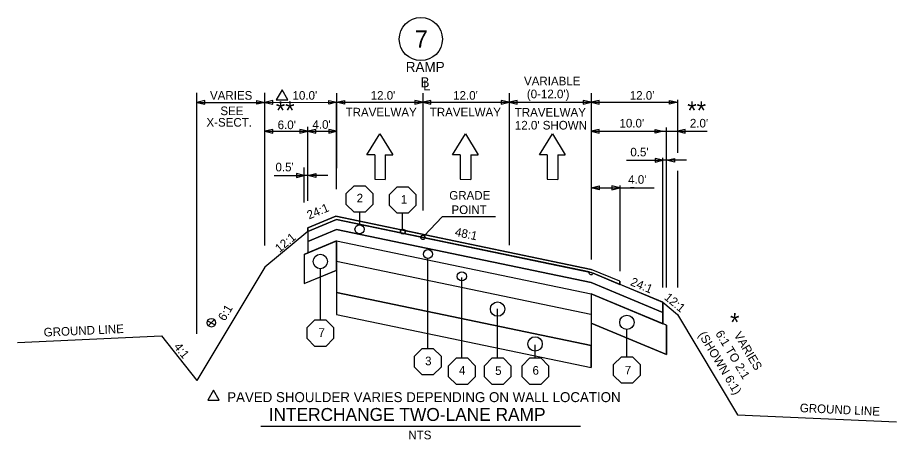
# Model space of a CAD drawing. Extents: x 4932 to 5887, y 4809 to 5473.
# Drawn here: x 5068.2 to 5190.4, y 5247.4 to 5306.2 of the extents above; entities that cross this region are included whole.
import ezdxf

# ---------------------------------------------------------------- set-up
doc = ezdxf.new("R2010")
doc.units = 0
for name, color, linetype in [('Level 20', 7, 'Continuous'), ('Level 25', 7, 'Continuous'), ('RD_QTY_Intermediate', 7, 'Continuous'), ('RD_QTY_OGFC', 7, 'Continuous'), ('RD_QTY_Stab_Agg_2', 7, 'Continuous'), ('RD_QTY_Sub_Base', 7, 'Continuous'), ('RD_QTY_Surf_Course', 7, 'Continuous'), ('RD_SHT_Typical', 7, 'Continuous'), ('RD_TX_TypSect', 7, 'Continuous'), ('RD_XS_ExGround', 7, 'Continuous'), ('typical_on', 7, 'Continuous')]:
    doc.layers.add(name, color=color, linetype=linetype)

msp = doc.modelspace()

# ---------------------------------------------------------------- linework, layer by layer
at = {"layer": 'Level 20'}
for p, q in [((5116.76, 5287.06), (5118.58, 5289.98)), ((5118.58, 5289.98), (5120.36, 5287.05)), ((5128.65, 5287.06), (5130.47, 5289.98)), ((5130.47, 5289.98), (5132.26, 5287.05)), ((5140.75, 5287.06), (5142.57, 5289.98)), ((5142.57, 5289.98), (5144.35, 5287.05)), ((5117.85, 5287.06), (5116.76, 5287.06)), ((5117.85, 5287.06), (5117.85, 5283.66)), ((5119.31, 5287.05), (5120.36, 5287.05)), ((5119.31, 5287.05), (5119.31, 5283.65)), ((5129.74, 5287.06), (5128.65, 5287.06)), ((5129.74, 5287.06), (5129.74, 5283.66)), ((5131.2, 5287.05), (5132.26, 5287.05)), ((5131.2, 5287.05), (5131.2, 5283.65)), ((5141.84, 5287.06), (5140.75, 5287.06)), ((5141.84, 5287.06), (5141.84, 5283.66)), ((5143.3, 5287.05), (5144.35, 5287.05)), ((5143.3, 5287.05), (5143.3, 5283.65)), ((5117.85, 5283.66), (5119.31, 5283.65)), ((5129.74, 5283.66), (5131.2, 5283.65)), ((5141.84, 5283.66), (5143.3, 5283.65))]:
    msp.add_line(p, q, dxfattribs=at)
at = {"layer": 'Level 25'}
for p, q in [((5127.23, 5278.45), (5124.75, 5275.8)), ((5134.63, 5278.45), (5127.23, 5278.45))]:
    msp.add_line(p, q, dxfattribs=at)
msp.add_circle((5124.27, 5303.18), 3, dxfattribs=at)
at = {"layer": 'RD_QTY_Intermediate'}
for p, q in [((5112.56, 5276.67), (5108.56, 5275)), ((5147.95, 5269.3), (5112.56, 5276.67)), ((5108.56, 5273.41), (5112.56, 5275.07)), ((5108.56, 5275), (5108.56, 5273.41)), ((5112.56, 5275.07), (5147.95, 5267.7)), ((5157.95, 5265.13), (5147.95, 5269.3)), ((5147.95, 5267.7), (5157.95, 5263.53)), ((5157.95, 5263.53), (5157.95, 5265.13))]:
    msp.add_line(p, q, dxfattribs=at)
at = {"layer": 'RD_QTY_OGFC'}
for p, q in [((5112.45, 5278.52), (5108.56, 5276.9)), ((5121.55, 5276.62), (5112.45, 5278.52)), ((5108.56, 5276.4), (5112.56, 5278.07)), ((5112.56, 5278.07), (5121.46, 5276.21)), ((5108.56, 5276.9), (5108.56, 5276.4))]:
    msp.add_line(p, q, dxfattribs=at)
msp.add_arc((5121.76, 5276.37), 0.332, 129.2008, 207.76, dxfattribs=at)
at = {"layer": 'RD_QTY_Stab_Agg_2'}
for p, q in [((5112.56, 5275.07), (5108.56, 5273.41)), ((5112.55, 5272.24), (5112.56, 5275.07)), ((5108.56, 5273.41), (5108.06, 5273.2)), ((5108.06, 5273.2), (5108.06, 5269.14)), ((5112.55, 5272.23), (5112.53, 5272.24)), ((5112.55, 5271.02), (5112.55, 5272.23)), ((5108.06, 5269.14), (5112.55, 5271.01)), ((5112.55, 5271.01), (5112.55, 5271.02)), ((5147.95, 5263.64), (5158.45, 5259.27)), ((5158.45, 5259.27), (5158.45, 5263.33))]:
    msp.add_line(p, q, dxfattribs=at)
for points in [[(5112.53, 5272.24), (5112.55, 5272.24)], [(5147.95, 5267.7), (5147.95, 5264.86), (5147.95, 5263.64)], [(5158.45, 5263.33), (5157.95, 5263.53), (5147.95, 5267.7)]]:
    msp.add_lwpolyline(points, dxfattribs=at)
at = {"layer": 'RD_QTY_Sub_Base'}
for p, q in [((5112.54, 5267.91), (5112.53, 5264.81)), ((5147.95, 5260.53), (5112.54, 5267.91)), ((5112.53, 5264.81), (5147.95, 5257.43)), ((5147.95, 5257.43), (5147.95, 5260.53))]:
    msp.add_line(p, q, dxfattribs=at)
at = {"layer": 'RD_QTY_Surf_Course'}
for p, q in [((5112.56, 5278.07), (5108.56, 5276.4)), ((5147.66, 5270.75), (5112.56, 5278.07)), ((5108.56, 5275), (5112.56, 5276.67)), ((5108.56, 5276.4), (5108.56, 5275)), ((5112.56, 5276.67), (5147.95, 5269.3)), ((5157.95, 5266.51), (5148.23, 5270.58)), ((5147.95, 5269.3), (5157.95, 5265.13)), ((5157.95, 5265.13), (5157.95, 5266.51))]:
    msp.add_line(p, q, dxfattribs=at)
msp.add_circle((5115.74, 5276.7), 0.63, dxfattribs=at)
msp.add_arc((5147.95, 5270.69), 0.3, 168.2335, 337.3133, dxfattribs=at)
at = {"layer": 'RD_SHT_Typical'}
for p, q in [((5108.56, 5276.9), (5112.45, 5278.52)), ((5108.56, 5276.4), (5112.56, 5278.07)), ((5108.56, 5276.4), (5102.57, 5271.4)), ((5108.56, 5276.4), (5108.56, 5276.9)), ((5108.56, 5275), (5112.56, 5276.67)), ((5108.56, 5276.4), (5108.56, 5273.41)), ((5121.96, 5276.11), (5124.26, 5275.63)), ((5124.87, 5275.93), (5122.05, 5276.52)), ((5124.75, 5275.8), (5124.87, 5275.93)), ((5124.87, 5275.93), (5124.75, 5275.8)), ((5147.95, 5271.12), (5124.87, 5275.93)), ((5108.06, 5273.2), (5112.58, 5275.08)), ((5112.53, 5275.09), (5112.53, 5264.81)), ((5124.85, 5275.51), (5147.66, 5270.75)), ((5108.06, 5273.2), (5108.06, 5269.14)), ((5102.57, 5271.4), (5093.12, 5255.66)), ((5108.06, 5269.14), (5112.58, 5271.02)), ((5151.95, 5269.45), (5147.95, 5271.12)), ((5151.95, 5269.45), (5147.95, 5271.12)), ((5147.66, 5270.75), (5147.95, 5270.69)), ((5157.95, 5266.53), (5147.95, 5270.69)), ((5157.95, 5265.13), (5147.95, 5269.3)), ((5151.95, 5269.45), (5151.95, 5269.03)), ((5151.95, 5269.03), (5151.95, 5269.45)), ((5147.95, 5267.7), (5147.95, 5257.43)), ((5158.45, 5263.33), (5147.95, 5267.7)), ((5157.95, 5266.53), (5159.95, 5264.85)), ((5157.95, 5266.51), (5157.95, 5263.53)), ((5158.45, 5259.27), (5147.95, 5263.64)), ((5159.95, 5264.85), (5168.33, 5250.88)), ((5158.45, 5263.33), (5158.45, 5259.27)), ((5088.18, 5261.84), (5093.12, 5255.66))]:
    msp.add_line(p, q, dxfattribs=at)
for points in [[(5112.45, 5278.52), (5147.95, 5271.12)], [(5112.56, 5278.07), (5147.95, 5270.69)], [(5112.56, 5276.67), (5147.95, 5269.3)], [(5112.56, 5275.07), (5147.95, 5267.7)], [(5124.75, 5275.8), (5124.75, 5275.8)], [(5112.53, 5272.24), (5147.93, 5264.86)], [(5147.95, 5270.69), (5148.23, 5270.58), (5151.95, 5269.02)], [(5151.95, 5269.02), (5151.95, 5269.03)], [(5112.53, 5267.91), (5147.95, 5260.53)], [(5112.53, 5264.81), (5147.95, 5257.43)]]:
    msp.add_lwpolyline(points, dxfattribs=at)
for centre, radius, start, end in [((5121.76, 5276.37), 0.332, 308.7071, 27.2663), ((5124.56, 5275.57), 0.3, 50.3399, 168.2335), ((5124.56, 5275.57), 0.3, 348.2335, 50.3399)]:
    msp.add_arc(centre, radius, start, end, dxfattribs=at)
at = {"layer": 'RD_TX_TypSect'}
for p, q in [((5093.12, 5262.15), (5093.12, 5295.7)), ((5102.57, 5274.42), (5102.57, 5295.7)), ((5112.56, 5295.67), (5112.56, 5285.2)), ((5124.56, 5295.67), (5124.56, 5279.32)), ((5136.55, 5295.67), (5136.55, 5274.5)), ((5147.95, 5295.67), (5147.95, 5272.5)), ((5093.12, 5294.37), (5102.57, 5294.37)), ((5102.57, 5294.37), (5112.56, 5294.38)), ((5112.56, 5282.28), (5112.56, 5294.5)), ((5112.56, 5294.38), (5124.56, 5294.38)), ((5124.56, 5294.38), (5136.55, 5294.38)), ((5136.55, 5294.38), (5147.95, 5294.38)), ((5147.95, 5294.38), (5159.95, 5294.38)), ((5159.95, 5294.72), (5159.95, 5287.35)), ((5108.56, 5280.64), (5108.56, 5290.96)), ((5158.45, 5268.57), (5158.45, 5290.87)), ((5102.57, 5290.34), (5108.56, 5290.34)), ((5108.56, 5290.34), (5112.56, 5290.34)), ((5147.95, 5290.34), (5157.95, 5290.34)), ((5157.95, 5290.34), (5159.95, 5290.34)), ((5159.95, 5290.34), (5164.09, 5290.34)), ((5152.86, 5286.3), (5157.95, 5286.3)), ((5157.95, 5268.57), (5157.95, 5286.64)), ((5161.21, 5286.3), (5157.95, 5286.3)), ((5108.06, 5280.41), (5108.06, 5285.28)), ((5159.95, 5284.84), (5159.95, 5268.57)), ((5103.88, 5284.2), (5108.06, 5284.2)), ((5111.33, 5284.2), (5108.06, 5284.2)), ((5147.95, 5282.47), (5156.71, 5282.47)), ((5151.95, 5282.81), (5151.95, 5270.86)), ((5153.95, 5282.47), (5153.45, 5282.47)), ((5115.74, 5279.08), (5115.74, 5277.34)), ((5121.74, 5276.7), (5121.74, 5278.94)), ((5125.23, 5260.11), (5125.23, 5272.61)), ((5110.29, 5264.08), (5110.29, 5271.21)), ((5129.97, 5258.78), (5129.97, 5269.96)), ((5134.94, 5258.78), (5134.94, 5265.6)), ((5094.59, 5263.95), (5095.66, 5263.41)), ((5094.71, 5263.26), (5095.54, 5264.11)), ((5152.93, 5258.94), (5152.93, 5262.74)), ((5140.18, 5258.78), (5140.18, 5260.63)), ((5102.02, 5249.3), (5146.48, 5249.3))]:
    msp.add_line(p, q, dxfattribs=at)
for points in [[(5104.96, 5296.11), (5104.16, 5294.73), (5105.75, 5294.73)], [(5094.22, 5294.1), (5094.22, 5294.65), (5093.12, 5294.37)], [(5101.46, 5294.1), (5101.46, 5294.65), (5102.57, 5294.37)], [(5103.67, 5294.1), (5103.67, 5294.65), (5102.57, 5294.37)], [(5111.46, 5294.1), (5111.46, 5294.65), (5112.56, 5294.38)], [(5113.66, 5294.65), (5113.66, 5294.1), (5112.56, 5294.38)], [(5123.45, 5294.65), (5123.45, 5294.1), (5124.56, 5294.38)], [(5125.66, 5294.1), (5125.66, 5294.65), (5124.56, 5294.38)], [(5135.45, 5294.65), (5135.45, 5294.1), (5136.55, 5294.38)], [(5137.66, 5294.1), (5137.66, 5294.65), (5136.55, 5294.38)], [(5146.85, 5294.65), (5146.85, 5294.1), (5147.95, 5294.38)], [(5149.05, 5294.1), (5149.05, 5294.65), (5147.95, 5294.38)], [(5158.84, 5294.1), (5158.84, 5294.65), (5159.95, 5294.38)], [(5103.67, 5290.06), (5103.67, 5290.61), (5102.57, 5290.34)], [(5107.46, 5290.61), (5107.46, 5290.06), (5108.56, 5290.34)], [(5109.67, 5290.06), (5109.67, 5290.61), (5108.56, 5290.34)], [(5111.46, 5290.61), (5111.46, 5290.06), (5112.56, 5290.34)], [(5149.05, 5290.06), (5149.05, 5290.61), (5147.95, 5290.34)], [(5156.84, 5290.06), (5156.84, 5290.61), (5157.95, 5290.34)], [(5161.05, 5290.06), (5161.05, 5290.61), (5159.95, 5290.34)], [(5156.84, 5286.57), (5156.84, 5286.02), (5157.95, 5286.3)], [(5159.55, 5286.57), (5159.55, 5286.02), (5158.45, 5286.3)], [(5106.96, 5284.47), (5106.96, 5283.92), (5108.06, 5284.2)], [(5109.67, 5284.47), (5109.67, 5283.92), (5108.56, 5284.2)], [(5149.05, 5282.75), (5149.05, 5282.2), (5147.95, 5282.47)], [(5150.85, 5282.75), (5150.85, 5282.2), (5151.95, 5282.47)], [(5095.42, 5254.3), (5094.62, 5252.91), (5096.22, 5252.91)]]:
    msp.add_lwpolyline(points, close=True, dxfattribs=at)
for centre, radius in [((5115.74, 5276.7), 0.63), ((5121.76, 5276.37), 0.332), ((5124.56, 5275.57), 0.3), ((5125.25, 5273.24), 0.63), ((5110.29, 5272.21), 1), ((5129.97, 5270.14), 0.63), ((5134.94, 5265.58), 1), ((5095.13, 5263.69), 0.6), ((5152.93, 5263.74), 1), ((5140.16, 5260.73), 1)]:
    msp.add_circle(centre, radius, dxfattribs=at)
at = {"layer": 'RD_XS_ExGround'}
for p, q in [((5068.18, 5260.93), (5088.21, 5261.84)), ((5168.33, 5250.88), (5190.42, 5249.88))]:
    msp.add_line(p, q, dxfattribs=at)
at = {"layer": 'typical_on'}
for points in [[(5117.59, 5281.69), (5117.59, 5280.16), (5116.51, 5279.08), (5114.98, 5279.08), (5113.9, 5280.16), (5113.9, 5281.69), (5114.98, 5282.77), (5116.51, 5282.77)], [(5123.59, 5281.55), (5123.59, 5280.02), (5122.51, 5278.94), (5120.98, 5278.94), (5119.89, 5280.02), (5119.89, 5281.55), (5120.98, 5282.63), (5122.5, 5282.63)], [(5112.14, 5263), (5112.14, 5261.47), (5111.06, 5260.39), (5109.53, 5260.39), (5108.45, 5261.47), (5108.45, 5263), (5109.53, 5264.08), (5111.06, 5264.08)], [(5127.08, 5259.02), (5127.08, 5257.49), (5126, 5256.41), (5124.47, 5256.41), (5123.39, 5257.49), (5123.39, 5259.02), (5124.47, 5260.11), (5126, 5260.11)], [(5131.82, 5257.7), (5131.82, 5256.17), (5130.74, 5255.09), (5129.21, 5255.09), (5128.13, 5256.17), (5128.13, 5257.7), (5129.21, 5258.78), (5130.74, 5258.78)], [(5136.79, 5257.7), (5136.79, 5256.17), (5135.71, 5255.09), (5134.18, 5255.09), (5133.1, 5256.17), (5133.1, 5257.7), (5134.18, 5258.78), (5135.71, 5258.78)], [(5142.03, 5257.7), (5142.03, 5256.17), (5140.95, 5255.09), (5139.42, 5255.09), (5138.34, 5256.17), (5138.34, 5257.7), (5139.42, 5258.78), (5140.95, 5258.78)], [(5154.77, 5257.86), (5154.77, 5256.33), (5153.69, 5255.25), (5152.16, 5255.25), (5151.08, 5256.33), (5151.08, 5257.86), (5152.16, 5258.94), (5153.69, 5258.94)]]:
    msp.add_lwpolyline(points, close=True, dxfattribs=at)

# ---------------------------------------------------------------- texts
at = {"layer": 'Level 25'}
for s, height, p in [('7', 2.4, (5123.44, 5301.98)), ('RAMP', 1.4, (5122.17, 5298.61)), ('B ', 1.4, (5124.22, 5296.47)), ('GRADE', 1.2, (5128.22, 5280.82)), ('POINT', 1.2, (5128.53, 5278.82))]:
    msp.add_text(s, height=height, rotation=0.0016, dxfattribs=at).set_placement(p)
at = {"layer": 'RD_TX_TypSect'}
for s, height, rotation, p in [('VARIABLE', 1.2, 0.0016, (5138.62, 5296.74)), ('L', 1.4, 0.0016, (5124.58, 5296.04)), ('VARIES', 1.2, 0.0016, (5094.94, 5294.74)), ("10.0'", 1.2, 0.0016, (5106.42, 5294.74)), ("12.0'", 1.2, 0.0016, (5117.29, 5294.74)), ("12.0'", 1.2, 0.0016, (5128.76, 5294.74)), ("(0-12.0')", 1.2, 0.0016, (5139.01, 5294.94)), ("12.0'", 1.2, 0.0016, (5153.33, 5294.74)), ('**', 2.5, 0.0016, (5104.1, 5292)), ('**', 2.5, 0.0016, (5161.33, 5292)), ('SEE', 1.2, 0.0016, (5096.39, 5292.59)), ('TRAVELWAY', 1.2, 0.0016, (5113.8, 5292.41)), ('TRAVELWAY', 1.2, 0.0016, (5125.51, 5292.41)), ('TRAVELWAY', 1.2, 0.0016, (5137.33, 5292.39)), ('X-SECT.', 1.2, 0.0016, (5094.45, 5290.99)), ("6.0'", 1.2, 0.0016, (5104.35, 5290.64)), ("4.0'", 1.2, 0.0016, (5109.19, 5290.69)), ("12.0' SHOWN", 1.2, 0.0016, (5137.35, 5290.59)), ("10.0'", 1.2, 0.0016, (5151.9, 5290.87)), ("2.0'", 1.2, 0.0016, (5161.69, 5290.87)), ("0.5'", 1.2, 0.0016, (5153.41, 5286.85)), ("0.5'", 1.2, 0.0016, (5104.05, 5284.76)), ("4.0'", 1.2, 0.0016, (5153.11, 5283.03)), ('2', 1.2, 0.0016, (5115.34, 5280.44)), ('1', 1.2, 0.0016, (5121.48, 5280.25)), ('24:1', 1.2, 22.6207, (5108.73, 5278.06)), ('12:1', 1.2, 39.8072, (5104.61, 5273.39)), ('48:1', 1.2, 348.2333, (5128.93, 5275.79)), ('24:1', 1.2, 337.3818, (5153.31, 5268.94)), ('12:1', 1.2, 320.1955, (5158.03, 5267.04)), ('6:1', 1.2, 59.0379, (5097.01, 5263.83)), ('*', 2.5, 0.0016, (5167.28, 5262.52)), ('GROUND LINE', 1.2, 2.6112, (5071.84, 5261.75)), ('7', 1.2, 0.0016, (5110.02, 5261.72)), ('6:1 TO 2:1', 1.2, 300.9654, (5165.19, 5262.19)), ('VARIES', 1.2, 300.9654, (5167.76, 5261.98)), ('(SHOWN 6:1)', 1.2, 300.9654, (5162.83, 5262.03)), ('4:1', 1.2, 308.6614, (5089.84, 5260.31)), ('3', 1.2, 0.0016, (5124.86, 5257.76)), ('4', 1.2, 0.0016, (5129.58, 5256.47)), ('5', 1.2, 0.0016, (5134.6, 5256.42)), ('6', 1.2, 0.0016, (5139.8, 5256.45)), ('7', 1.2, 0.0016, (5152.64, 5256.48)), ('PAVED SHOULDER VARIES DEPENDING ON WALL LOCATION', 1.3845, 0.0016, (5097.33, 5252.63)), ('INTERCHANGE TWO-LANE RAMP', 1.8, 0.0016, (5103.1, 5250.01)), ('GROUND LINE', 1.2, 357.3921, (5176.96, 5251.24)), ('NTS', 1.2, 0.0016, (5122.53, 5247.45))]:
    msp.add_text(s, height=height, rotation=rotation, dxfattribs=at).set_placement(p)

doc.saveas('drawing.dxf')
